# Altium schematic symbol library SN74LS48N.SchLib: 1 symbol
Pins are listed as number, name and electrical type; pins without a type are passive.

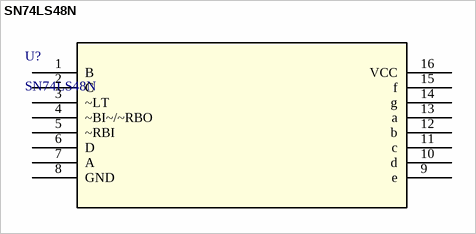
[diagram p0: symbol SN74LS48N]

## SN74LS48N
designator U?
No Description Available; Manufacturer_Name: Texas Instruments
footprint DIP16_300
pins: 1 B, 2 C, 3 ~LT, 4 ~BI~/~RBO, 5 ~RBI, 6 D, 7 A, 8 GND, 9 e, 10 d, 11 c, 12 b, 13 a, 14 g, 15 f, 16 VCC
